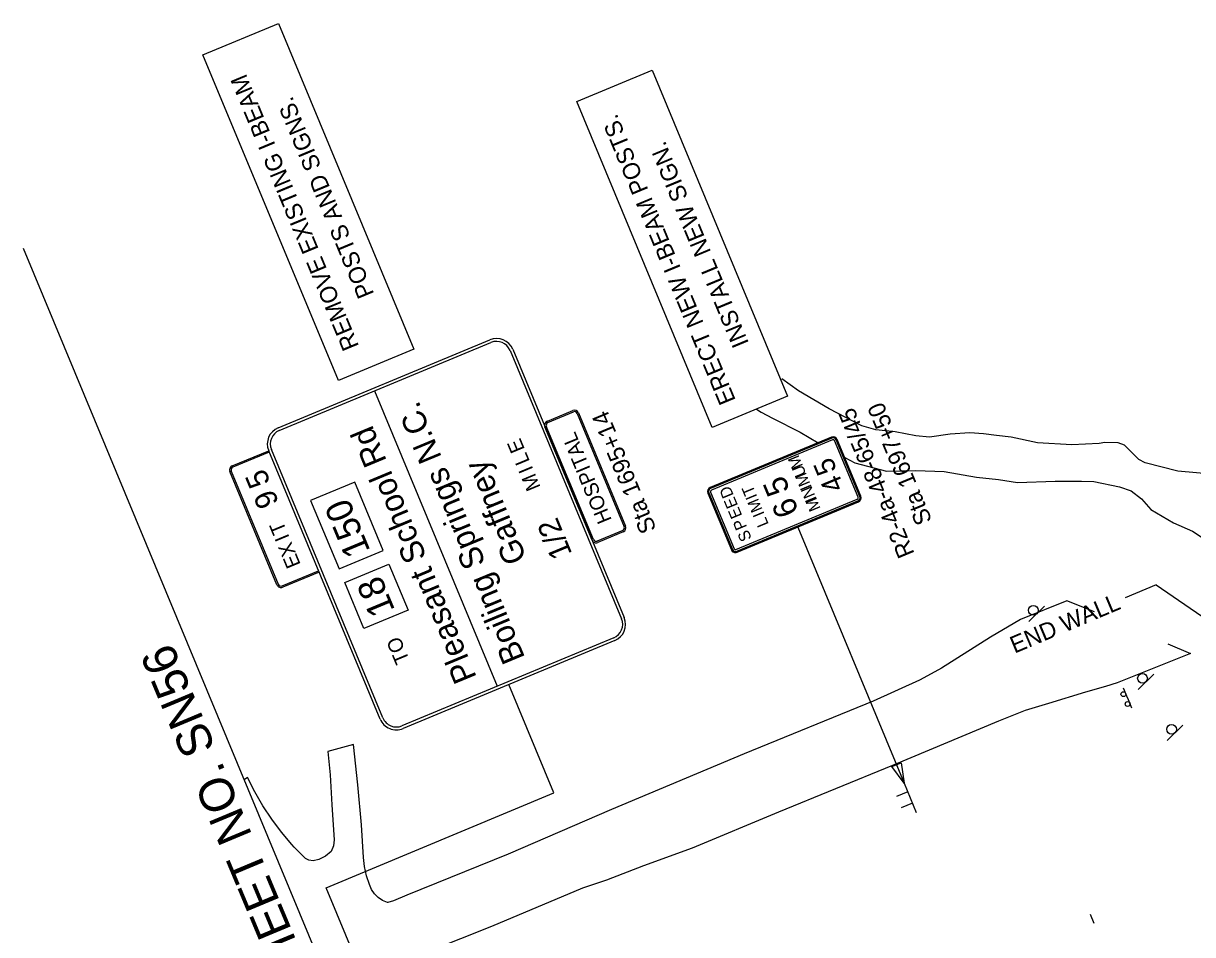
# Model space of a CAD drawing. Extents: x 1816080 to 1817753, y 1191002 to 1192408.
# Drawn here: x 1816080.2 to 1816560.8, y 1191507.4 to 1191881.9 of the extents above; entities that cross this region are included whole.
import ezdxf

# ---------------------------------------------------------------- set-up
doc = ezdxf.new("R2010")
doc.units = 0
for name, color, linetype in [('RD_EX_H2O', 7, 'Continuous'), ('RD_EX_Road', 7, 'Continuous'), ('RD_PD_Final_TX', 7, 'Continuous'), ('RD_SHT_MatchLine', 7, 'Continuous'), ('RD_SHT_TX', 7, 'Continuous'), ('SN_P_Signs', 7, 'Continuous')]:
    doc.layers.add(name, color=color, linetype=linetype)

msp = doc.modelspace()

# ---------------------------------------------------------------- linework, layer by layer
at = {"layer": 'RD_EX_H2O'}
for points in [[(1816522.41, 1191709.25), (1816511.17, 1191708.66), (1816497.01, 1191709.47), (1816486.18, 1191711.86), (1816480.27, 1191712.47), (1816474.86, 1191713.22), (1816469.32, 1191713.68), (1816461.18, 1191713.14), (1816452.7, 1191711.8), (1816447.05, 1191712.4), (1816438.53, 1191713.99), (1816430.58, 1191714.91), (1816424.88, 1191716.5), (1816411.41, 1191723.48), (1816398.88, 1191730.96), (1816391.91, 1191735.8)], [(1816381.56, 1191723.42), (1816383.47, 1191722.16), (1816388.11, 1191719.6), (1816399.51, 1191713.88), (1816406.9, 1191709.58)], [(1816589, 1191679.78), (1816585.25, 1191683.2), (1816578.74, 1191691.77), (1816573.75, 1191694.47), (1816568.64, 1191696.6), (1816554.75, 1191697.91), (1816541.33, 1191701.27), (1816538.68, 1191702.62), (1816532.83, 1191708.56), (1816530.28, 1191709.54), (1816524.78, 1191709.72), (1816522.41, 1191709.25)], [(1816417.81, 1191703.51), (1816422.01, 1191701.25), (1816434.93, 1191697.85), (1816447.06, 1191698.2), (1816458.77, 1191697.78), (1816471.93, 1191695.43), (1816481.08, 1191694.51), (1816488.89, 1191693.18), (1816504.34, 1191693.79), (1816515.11, 1191693.78), (1816520.29, 1191693.6)], [(1816520.29, 1191693.6), (1816530.82, 1191691.49), (1816535.64, 1191689.78), (1816539.88, 1191686.46), (1816543.67, 1191682.18), (1816552.98, 1191676.66), (1816560.73, 1191673.18), (1816565.63, 1191670.1)]]:
    msp.add_lwpolyline(points, dxfattribs=at)
at = {"layer": 'RD_EX_Road'}
for points in [[(1816520.52, 1191640.01), (1816509.14, 1191644.64), (1816490.04, 1191636.88), (1816477.79, 1191629.66), (1816457.56, 1191616.88), (1816451.92, 1191613.7), (1816448.56, 1191611.92), (1816429.46, 1191603.4), (1816376.47, 1191581.65), (1816321.89, 1191558.78), (1816279.43, 1191540.48), (1816237.83, 1191523.6), (1816232.28, 1191521.34), (1816230.07, 1191520.56), (1816229.85, 1191520.63), (1816227.86, 1191521.48), (1816226.06, 1191522.69), (1816224.51, 1191524.19), (1816223.26, 1191525.96), (1816222.4, 1191528), (1816221.22, 1191531.62), (1816220.42, 1191535.35), (1816220.02, 1191539.14), (1816219.15, 1191552.45), (1816217.71, 1191569.02), (1816215.88, 1191585.54), (1816205.29, 1191582.59), (1816206.29, 1191573), (1816207.03, 1191560.74), (1816207.95, 1191546.35), (1816207.66, 1191543.89), (1816206.76, 1191541.59), (1816204.37, 1191539.57), (1816202.77, 1191538.83), (1816201.69, 1191538.26), (1816199.35, 1191537.69), (1816197.57, 1191537.96), (1816196.16, 1191538.74), (1816191.54, 1191543.37), (1816190.54, 1191544.46), (1816186.26, 1191549.52), (1816182.29, 1191554.83), (1816178.65, 1191560.36), (1816175.34, 1191566.1), (1816172.37, 1191572.03), (1816170.97, 1191570.99)], [(1816550.6, 1191626.95), (1816559.95, 1191622.95), (1816529.85, 1191610.9), (1816525.09, 1191609.33), (1816516.83, 1191607.04), (1816501.56, 1191602.44), (1816492, 1191599.57), (1816481.01, 1191595.11), (1816437.42, 1191576.88), (1816390.61, 1191557.7), (1816355.1, 1191542.99), (1816335.12, 1191535.64), (1816319.86, 1191529.84), (1816310.03, 1191526.5), (1816272.57, 1191510.76), (1816235.07, 1191495.79), (1816207.01, 1191484.27)]]:
    msp.add_lwpolyline(points, dxfattribs=at)
at = {"layer": 'RD_PD_Final_TX'}
for q in [(1816533.11, 1191645.81), (1816580.76, 1191627.24)]:
    msp.add_line((1816545.83, 1191651.16), q, dxfattribs=at)
at = {"layer": 'RD_SHT_MatchLine'}
msp.add_line((1816407.28, 1191002.35), (1816080.19, 1191789.44), dxfattribs=at)
at = {"layer": 'SN_P_Signs'}
for p, q in [((1816154.02, 1191869.02), (1816185.07, 1191881.92)), ((1816185.07, 1191881.92), (1816240.72, 1191748)), ((1816209.68, 1191735.1), (1816154.02, 1191869.02)), ((1816307.65, 1191849.75), (1816338.69, 1191862.65)), ((1816338.69, 1191862.65), (1816394.34, 1191728.73)), ((1816363.3, 1191715.83), (1816307.65, 1191849.75)), ((1816240.72, 1191748), (1816209.68, 1191735.1)), ((1816224.5, 1191730.85), (1816274.95, 1191609.46)), ((1816394.34, 1191728.73), (1816363.3, 1191715.83)), ((1816295.58, 1191718.45), (1816306.06, 1191722.8)), ((1816295.81, 1191717.89), (1816306.29, 1191722.25)), ((1816412.39, 1191711.86), (1816362.53, 1191691.14)), ((1816424.42, 1191687.62), (1816414.75, 1191710.89)), ((1816216.43, 1191693.39), (1816198.25, 1191685.84)), ((1816228.13, 1191665.25), (1816216.43, 1191693.39)), ((1816361.56, 1191688.78), (1816371.23, 1191665.51)), ((1816198.25, 1191685.84), (1816209.95, 1191657.69)), ((1816373.58, 1191664.54), (1816423.45, 1191685.26)), ((1816398.51, 1191674.9), (1816442.23, 1191569.7)), ((1816326.55, 1191673.49), (1816316.07, 1191669.14)), ((1816326.78, 1191672.94), (1816316.3, 1191668.58)), ((1816209.95, 1191657.69), (1816228.13, 1191665.25)), ((1816212.28, 1191652.09), (1816230.46, 1191659.64)), ((1816230.46, 1191659.64), (1816238.32, 1191640.73)), ((1816220.14, 1191633.18), (1816212.28, 1191652.09)), ((1816238.32, 1191640.73), (1816220.14, 1191633.18)), ((1816493.56, 1191636.07), (1816499.93, 1191642.44)), ((1816538.48, 1191608.11), (1816544.84, 1191614.47)), ((1816298.31, 1191565.61), (1816279.8, 1191610.17)), ((1816534.18, 1191604.51), (1816532.48, 1191608.68)), ((1816535.9, 1191600.47), (1816534.19, 1191604.63)), ((1816550.42, 1191587.17), (1816556.78, 1191593.54)), ((1816442.23, 1191569.7), (1816447.24, 1191557.65)), ((1816204.66, 1191526.69), (1816298.31, 1191565.61)), ((1816443.73, 1191566.09), (1816439.13, 1191564.17)), ((1816445.66, 1191561.45), (1816441.05, 1191559.54)), ((1816221.98, 1191484.99), (1816204.66, 1191526.69)), ((1816520.36, 1191511.99), (1816518.83, 1191515.68))]:
    msp.add_line(p, q, dxfattribs=at)
for points in [[(1816184.91, 1191715.7), (1816271.95, 1191751.87)], [(1816185.37, 1191714.59), (1816272.41, 1191750.76)], [(1816280.25, 1191747.52), (1816326.09, 1191637.21)], [(1816281.36, 1191747.98), (1816327.2, 1191637.67)], [(1816308.41, 1191721.83), (1816327.75, 1191675.29)], [(1816307.86, 1191721.6), (1816327.2, 1191675.06)], [(1816313.95, 1191669.55), (1816294.61, 1191716.1)], [(1816314.5, 1191669.78), (1816295.16, 1191716.33)], [(1816412.57, 1191711.44), (1816362.7, 1191690.72)], [(1816412.85, 1191710.75), (1816362.99, 1191690.03)], [(1816423.31, 1191687.16), (1816413.64, 1191710.43)], [(1816424, 1191687.44), (1816414.33, 1191710.71)], [(1816166.06, 1191700.07), (1816181.02, 1191706.28), (1816181.25, 1191705.73)], [(1816181.25, 1191705.73), (1816166.29, 1191699.51)], [(1816226.87, 1191595.97), (1816181.02, 1191706.28)], [(1816227.97, 1191596.43), (1816182.13, 1191706.74)], [(1816184.43, 1191651.17), (1816165.09, 1191697.71)], [(1816165.65, 1191697.94), (1816184.99, 1191651.4)], [(1816361.97, 1191688.96), (1816371.64, 1191665.69)], [(1816362.67, 1191689.24), (1816372.34, 1191665.97)], [(1816373.12, 1191665.65), (1816422.99, 1191686.37)], [(1816373.41, 1191664.96), (1816423.27, 1191685.68)], [(1816186.56, 1191650.76), (1816201.52, 1191656.97), (1816201.75, 1191656.42), (1816186.79, 1191650.2)], [(1816322.85, 1191629.37), (1816235.82, 1191593.19)], [(1816323.31, 1191628.26), (1816236.28, 1191592.09)]]:
    msp.add_lwpolyline(points, dxfattribs=at)
msp.add_lwpolyline([(1816440.98, 1191578.06), (1816442.23, 1191569.7), (1816437.19, 1191576.48)], close=True, dxfattribs=at)
for centre, radius in [((1816495.32, 1191640.7), 2), ((1816540.24, 1191612.74), 2), ((1816532.39, 1191606.22), 1), ((1816534.11, 1191602.18), 1), ((1816552.18, 1191591.8), 2)]:
    msp.add_circle(centre, radius, dxfattribs=at)
for centre, radius, start, end in [((1816274.71, 1191745.22), 7.2, 22.5666, 112.5666), ((1816274.71, 1191745.22), 6, 22.5666, 112.5666), ((1816306.75, 1191721.14), 1.8, 22.5666, 112.5666), ((1816306.75, 1191721.14), 1.2, 22.5666, 112.5666), ((1816296.27, 1191716.79), 1.8, 112.5666, 202.5666), ((1816296.27, 1191716.79), 1.2, 112.5666, 202.5666), ((1816187.67, 1191709.05), 7.2, 112.5666, 202.5666), ((1816187.67, 1191709.05), 6, 112.5666, 202.5666), ((1816413.08, 1191710.2), 1.8, 22.5666, 112.5666), ((1816413.08, 1191710.2), 1.35, 22.5666, 112.5666), ((1816413.08, 1191710.2), 0.6, 22.5666, 112.5666), ((1816166.75, 1191698.4), 1.8, 112.5666, 202.5666), ((1816166.75, 1191698.4), 1.2, 112.5666, 202.5666), ((1816363.22, 1191689.47), 1.8, 112.5666, 202.5666), ((1816363.22, 1191689.47), 1.35, 112.5666, 202.5666), ((1816363.22, 1191689.47), 0.6, 112.5666, 202.5666), ((1816422.76, 1191686.93), 0.6, 292.5666, 22.5666), ((1816422.76, 1191686.93), 1.35, 292.5666, 22.5666), ((1816422.76, 1191686.93), 1.8, 292.5666, 22.5666), ((1816326.09, 1191674.6), 1.2, 292.5666, 22.5666), ((1816326.09, 1191674.6), 1.8, 292.5666, 22.5666), ((1816315.61, 1191670.25), 1.8, 202.5666, 292.5666), ((1816315.61, 1191670.25), 1.2, 202.5666, 292.5666), ((1816372.89, 1191666.2), 1.8, 202.5666, 292.5666), ((1816372.89, 1191666.2), 1.35, 202.5666, 292.5666), ((1816372.89, 1191666.2), 0.6, 202.5666, 292.5666), ((1816186.09, 1191651.86), 1.8, 202.5666, 292.5666), ((1816186.09, 1191651.86), 1.2, 202.5666, 292.5666), ((1816320.55, 1191634.91), 6, 292.5666, 22.5666), ((1816320.55, 1191634.91), 7.2, 292.5666, 22.5666), ((1816233.51, 1191598.74), 7.2, 202.5666, 292.5666), ((1816233.51, 1191598.74), 6, 202.5666, 292.5666)]:
    msp.add_arc(centre, radius, start, end, dxfattribs=at)

# ---------------------------------------------------------------- texts
at = {"layer": 'RD_PD_Final_TX'}
msp.add_text('END WALL', height=7, rotation=22.8166, dxfattribs=at).set_placement((1816487.63, 1191622.84))
at = {"layer": 'RD_SHT_TX'}
msp.add_text('MATCHLINE STA. 1695+00 SEE SHEET NO. SN56', height=14.1726, rotation=112.6789, dxfattribs=at).set_placement((1816310.65, 1191222.14))
at = {"layer": 'SN_P_Signs'}
for s, height, rotation, p in [('REMOVE EXISTING I-BEAM', 6.9998, 112.5667, (1816218.27, 1191749.23)), ('POSTS AND SIGNS.', 6.9998, 112.5667, (1816224.51, 1191770.71)), ('ERECT NEW I-BEAM POSTS.', 6.9998, 112.5667, (1816373.13, 1191727.01)), ('INSTALL NEW SIGN.', 6.9998, 112.5667, (1816378.55, 1191750.44)), ('Boiling Springs N.C.', 9.6, 112.5666, (1816286.54, 1191621.18)), ('Sta 1695+14', 7, 112.5667, (1816340.55, 1191674.02)), ('R2-4a-48-65/45', 7, 112.5667, (1816446.61, 1191663.99)), ('Sta 1697+50', 7, 112.5667, (1816453.87, 1191677.51)), ('Pleasant School Rd', 9.6, 112.5666, (1816266.66, 1191613.12)), ('HOSPITAL', 6, 112.5666, (1816322.16, 1191677.82)), ('E', 6, 112.5666, (1816286.42, 1191706.88)), ('L', 6, 112.5666, (1816288.5, 1191701.87)), ('M', 4.8, 112.5666, (1816400.76, 1191699.97)), ('5', 8.4, 112.5666, (1816414.75, 1191698.38)), ('5', 9, 112.5666, (1816181.88, 1191693.27)), ('Gaffney', 9.6, 112.5666, (1816287.28, 1191661.92)), ('I', 6, 112.5666, (1816289.88, 1191698.56)), ('U', 4.8, 112.5666, (1816402.16, 1191696.62)), ('M', 6, 112.5666, (1816292.9, 1191691.29)), ('5', 9.6, 112.5666, (1816395.44, 1191690.13)), ('M', 4.8, 112.5666, (1816403.74, 1191692.81)), ('4', 8.4, 112.5666, (1816417.72, 1191691.23)), ('9', 9, 112.5666, (1816185.37, 1191684.87)), ('D', 4.8, 112.5666, (1816372.29, 1191687.97)), ('T', 4.8, 112.5666, (1816381.27, 1191689.03)), ('I', 4.8, 112.5666, (1816381.97, 1191687.36)), ('I', 4.8, 112.5666, (1816404.39, 1191691.25)), ('N', 4.8, 112.5666, (1816405.78, 1191687.9)), ('150', 10.8, 112.5666, (1816222.94, 1191665.15)), ('E', 4.8, 112.5666, (1816374.03, 1191683.77)), ('E', 4.8, 112.5666, (1816375.78, 1191679.58)), ('M', 4.8, 112.5666, (1816384.14, 1191682.13)), ('6', 9.6, 112.5666, (1816399.13, 1191681.23)), ('I', 4.8, 112.5666, (1816406.43, 1191686.34)), ('M', 4.8, 112.5666, (1816408.01, 1191682.53)), ('1/2', 9, 112.5666, (1816305.9, 1191663.91)), ('I', 4.8, 112.5666, (1816384.93, 1191680.22)), ('L', 4.8, 112.5666, (1816386.66, 1191676.05)), ('T', 6, 112.5666, (1816188.54, 1191673.33)), ('P', 4.8, 112.5666, (1816377.74, 1191674.87)), ('I', 6, 112.5666, (1816189.69, 1191670.57)), ('X', 6, 112.5666, (1816192.3, 1191664.28)), ('S', 4.8, 112.5666, (1816379.69, 1191670.16)), ('E', 6, 112.5666, (1816194.28, 1191659.52)), ('18', 10.8, 112.5666, (1816233.07, 1191640.76)), ('TO', 6, 112.5666, (1816239.05, 1191620.09))]:
    msp.add_text(s, height=height, rotation=rotation, dxfattribs=at).set_placement(p)

doc.saveas('drawing.dxf')
